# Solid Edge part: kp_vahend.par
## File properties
Author: Georg
Template: Iso Metric Part.par
Last saved by: Georg
Revision: 6
Application: Solid Edge
Accuracy: 0,990
Face Style: Model Default
Fill Style: Normal
Coef. of Thermal Exp: 0.0
Thermal Conductivity: 0.0
Specific Heat: 0.0
Modulus of Elasticity: 0.0
Poisson's Ratio: 0.0
Yield Stress: 0.0
Ultimate Stress: 0.0
Elongation: 0.0
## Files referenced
!C:\Users\Georg\Desktop\lennuk.asm
..\lennuk.asm
C:\Users\Georg\Desktop\kuulipilduri_haoidja.par
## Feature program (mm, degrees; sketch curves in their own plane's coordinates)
sketch for "unnamed Protrusion 1" #1 plane through (0, 0, 0) normal (1, 0, 0) x-axis (0, 1, 0)
  circle centre (4420.2777, -620) radius 15
sketch for "unnamed Protrusion 1" #2 plane through (0, 0, 0) normal (1, 0, 0) x-axis (0, 1, 0)
  line (4420.2777, -570) -> (4350.2777, -570)
  line (4350.2777, -570) -> (4350.2777, -670)
  line (4350.2777, -670) -> (4420.2777, -670)
extrude "unnamed Protrusion 1" add finite 70 symmetric
sketch for "unnamed Protrusion 2" plane through (35, 4410.2777, -620) normal (1, 0, 0) x-axis (0, 1, 0)
  circle centre (10, 0) radius 15
extrude "unnamed Protrusion 2" add to key point along -normal
sketch for "unnamed Protrusion 3" plane through (35, 4410.2777, -620) normal (1, 0, 0) x-axis (0, 1, 0)
  circle centre (10, 0) radius 15
extrude "unnamed Protrusion 3" add to key point along +normal
sketch for "ExtrudedCutout_1" plane through (0, 4350.2777, -620) normal (0, -1, 0) x-axis (-1, 0, 0)
  circle centre (0, 0) radius 10
extrude "ExtrudedCutout_1" cut finite 10 along -normal
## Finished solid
Body 1: solid body, 12 faces, 18 edges, 8 vertices.
  Faces by surface: plane 8, cylinder 4
  Edges by curve: line 10, circle 8
Bounding box of the edges (mm): 125.000 x 120.000 x 100.000, from (-62.5, 4350.2777, -670) to (62.5, 4470.2777, -570).
Cylindrical faces by radius (mm): R10 x1, R15 x2, R50 x1
Planar faces by outward normal: +x 2, +z 1, -x 2, -y 2, -z 1
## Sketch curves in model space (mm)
circle centre (35, 4420.2777, -620) radius 15
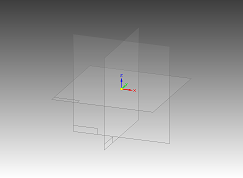
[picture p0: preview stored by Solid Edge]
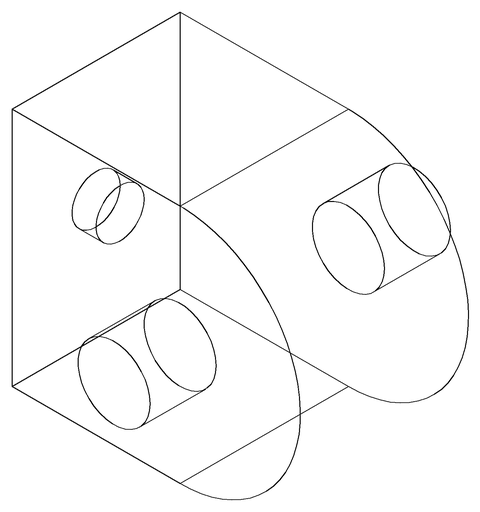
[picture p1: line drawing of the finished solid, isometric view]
